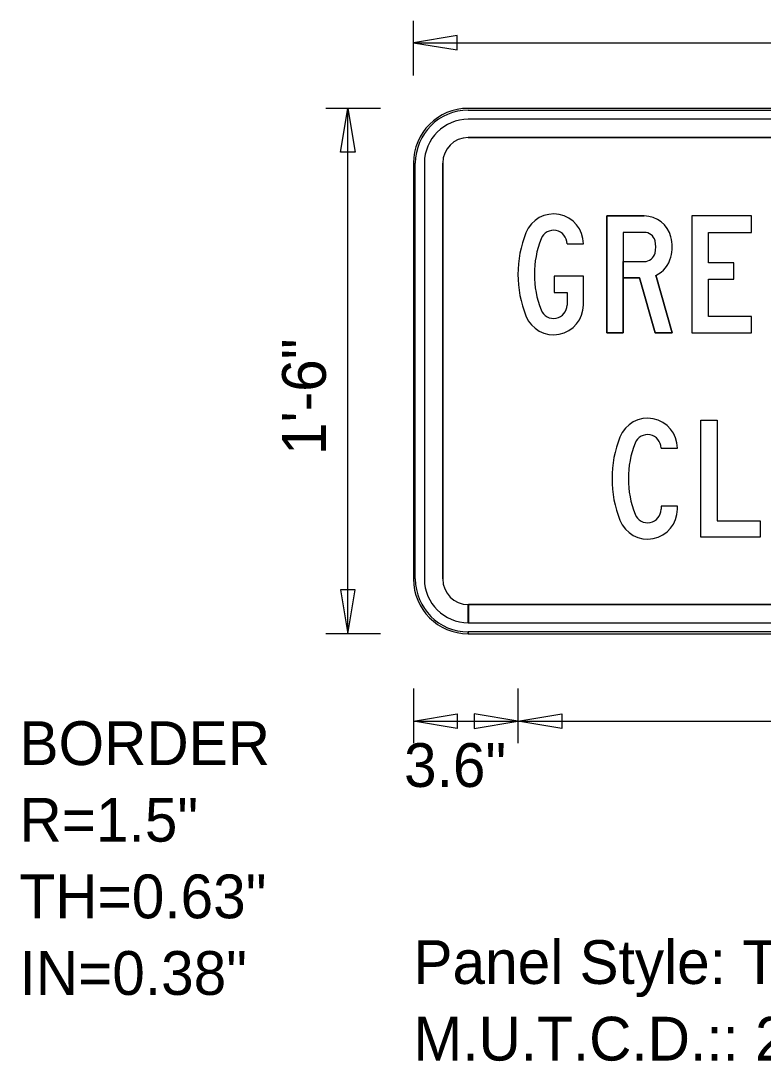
# Model space of a CAD drawing. Extents: x 1788.1 to 1851.2, y 237.2 to 283.4.
# Drawn here: x 1838.393 to 1840.936, y 274.583 to 278.148 of the extents above; entities that cross this region are included whole.
import ezdxf

# ---------------------------------------------------------------- set-up
doc = ezdxf.new("R2010")
doc.units = 0
for name, color, linetype in [('GSBWFILL', 7, 'Continuous'), ('GSCOLORFILL', 7, 'Continuous'), ('GSDIMS', 7, 'Continuous'), ('GSOUTLINE', 7, 'Continuous')]:
    doc.layers.add(name, color=color, linetype=linetype)

msp = doc.modelspace()

# ---------------------------------------------------------------- linework, layer by layer
at = {"layer": 'GSBWFILL'}
for p, q in [((1842.5504, 277.848), (1839.9254, 277.848)), ((1842.5504, 277.8105), (1839.9254, 277.8105)), ((1839.9254, 277.748), (1842.5504, 277.748)), ((1839.7379, 277.6605), (1839.7379, 276.2355)), ((1839.7754, 277.6605), (1839.7754, 276.2355)), ((1839.8379, 276.2355), (1839.8379, 277.6605)), ((1840.2639, 277.3842), (1840.3199, 277.3842)), ((1840.5284, 277.3232), (1840.5284, 277.3232)), ((1840.2639, 277.2172), (1840.2639, 277.1742)), ((1840.5859, 276.6842), (1840.6419, 276.6842)), ((1839.9254, 276.0855), (1839.9254, 276.148)), ((1842.5504, 276.148), (1839.926, 276.148)), ((1839.926, 276.148), (1839.926, 276.0855)), ((1839.926, 276.0855), (1842.5504, 276.0855)), ((1839.9254, 276.048), (1842.5504, 276.048))]:
    msp.add_line(p, q, dxfattribs=at)
for points in [[(1840.5284, 277.4232), (1840.4559, 277.4232), (1840.4559, 277.0792), (1840.3999, 277.0792), (1840.3999, 277.4792), (1840.5284, 277.4792)], [(1840.5679, 277.2759), (1840.6239, 277.0792), (1840.5657, 277.0792), (1840.5121, 277.2672), (1840.4559, 277.2672), (1840.4559, 277.3232), (1840.5284, 277.3232)], [(1840.3199, 277.1742), (1840.3199, 277.2732), (1840.2199, 277.2732), (1840.2199, 277.2172), (1840.2639, 277.2172)], [(1840.6419, 276.4742), (1840.6419, 276.4852), (1840.5859, 276.4852), (1840.5859, 276.4742)]]:
    msp.add_lwpolyline(points, dxfattribs=at)
for points in [[(1840.7479, 277.1352), (1840.7479, 277.2632), (1840.8355, 277.2632), (1840.8355, 277.3192), (1840.7479, 277.3192), (1840.7479, 277.4232), (1840.8959, 277.4232), (1840.8959, 277.4792), (1840.6919, 277.4792), (1840.6919, 277.0792), (1840.8959, 277.0792), (1840.8959, 277.1352)], [(1840.7219, 276.7792), (1840.7779, 276.7792), (1840.7779, 276.4352), (1840.9259, 276.4352), (1840.9259, 276.3792), (1840.7219, 276.3792)]]:
    msp.add_lwpolyline(points, close=True, dxfattribs=at)
for centre, radius, start, end in [((1839.9254, 277.6605), 0.1875, 90, 180), ((1839.9254, 277.6605), 0.15, 90, 180), ((1839.9254, 277.6605), 0.0875, 90, 180), ((1840.5284, 277.3852), 0.094, 13.8865, 90), ((1840.5284, 277.3852), 0.038, 13.8865, 90), ((1840.4799, 277.3732), 0.144, 346.1135, 13.8865), ((1840.4799, 277.3732), 0.088, 346.1135, 13.8865), ((1840.5284, 277.3612), 0.038, 270, 346.1135), ((1840.5284, 277.3612), 0.094, 294.8221, 346.1135), ((1840.5399, 276.6842), 0.102, 0, 158.4314), ((1840.5399, 276.6842), 0.046, 0, 158.4314), ((1840.8055, 276.5792), 0.3876, 158.4314, 201.5686), ((1840.8055, 276.5792), 0.3316, 158.4314, 201.5686), ((1840.5399, 276.4742), 0.102, 201.5686, 0), ((1840.5399, 276.4742), 0.046, 201.5686, 0), ((1839.9254, 276.2355), 0.1875, 180, 270), ((1839.9254, 276.2355), 0.15, 180, 270), ((1839.9254, 276.2355), 0.0875, 180, 270)]:
    msp.add_arc(centre, radius, start, end, dxfattribs=at)
for centre, major_axis, start_param, end_param in [((1840.2179, 277.3842), (0, 0.102), 4.712389, 7.477539), ((1840.4835, 277.2792), (0, 0.3876), 1.194353, 1.947239), ((1840.4835, 277.2792), (0, 0.3316), 1.194353, 1.947239), ((1840.2179, 277.3842), (0, 0.046), 4.712389, 7.477539), ((1840.2179, 277.1742), (0, 0.102), 1.947239, 4.712389), ((1840.2179, 277.1742), (0, 0.046), 1.947239, 4.712389)]:
    msp.add_ellipse(centre, major_axis=major_axis, ratio=0.999991, start_param=start_param, end_param=end_param, dxfattribs=at)
at = {"layer": 'GSCOLORFILL'}
for p, q in [((1842.5504, 277.848), (1839.9254, 277.848)), ((1842.5504, 277.848), (1839.9254, 277.848)), ((1839.9254, 277.8417), (1842.5504, 277.8417)), ((1842.5504, 277.8105), (1839.9254, 277.8105)), ((1839.9254, 277.748), (1842.5504, 277.748)), ((1839.7379, 277.6605), (1839.7379, 276.2355)), ((1839.7379, 277.6605), (1839.7379, 276.2355)), ((1839.7441, 276.2355), (1839.7441, 277.6605)), ((1839.7754, 277.6605), (1839.7754, 276.2355)), ((1839.8379, 276.2355), (1839.8379, 277.6605)), ((1840.2639, 277.3842), (1840.3199, 277.3842)), ((1840.5284, 277.3232), (1840.5284, 277.3232)), ((1840.2639, 277.2172), (1840.2639, 277.1742)), ((1840.5859, 276.6842), (1840.6419, 276.6842)), ((1839.9254, 276.0855), (1839.9254, 276.148)), ((1842.5504, 276.148), (1839.926, 276.148)), ((1839.926, 276.148), (1839.926, 276.0855)), ((1839.926, 276.0855), (1842.5504, 276.0855)), ((1839.9254, 276.048), (1839.9254, 276.0542)), ((1839.9254, 276.048), (1842.5504, 276.048)), ((1842.5504, 276.0542), (1839.9255, 276.0542)), ((1839.9255, 276.0542), (1839.9255, 276.048)), ((1839.9255, 276.048), (1842.5504, 276.048))]:
    msp.add_line(p, q, dxfattribs=at)
for points in [[(1840.5284, 277.4232), (1840.4559, 277.4232), (1840.4559, 277.0792), (1840.3999, 277.0792), (1840.3999, 277.4792), (1840.5284, 277.4792)], [(1840.5679, 277.2759), (1840.6239, 277.0792), (1840.5657, 277.0792), (1840.5121, 277.2672), (1840.4559, 277.2672), (1840.4559, 277.3232), (1840.5284, 277.3232)], [(1840.3199, 277.1742), (1840.3199, 277.2732), (1840.2199, 277.2732), (1840.2199, 277.2172), (1840.2639, 277.2172)], [(1840.6419, 276.4742), (1840.6419, 276.4852), (1840.5859, 276.4852), (1840.5859, 276.4742)]]:
    msp.add_lwpolyline(points, dxfattribs=at)
for points in [[(1840.7479, 277.1352), (1840.7479, 277.2632), (1840.8355, 277.2632), (1840.8355, 277.3192), (1840.7479, 277.3192), (1840.7479, 277.4232), (1840.8959, 277.4232), (1840.8959, 277.4792), (1840.6919, 277.4792), (1840.6919, 277.0792), (1840.8959, 277.0792), (1840.8959, 277.1352)], [(1840.7219, 276.7792), (1840.7779, 276.7792), (1840.7779, 276.4352), (1840.9259, 276.4352), (1840.9259, 276.3792), (1840.7219, 276.3792)]]:
    msp.add_lwpolyline(points, close=True, dxfattribs=at)
for centre, radius, start, end in [((1839.9254, 277.6605), 0.1875, 90, 180), ((1839.9254, 277.6605), 0.1875, 90, 180), ((1839.9254, 277.6605), 0.1812, 90, 180), ((1839.9254, 277.6605), 0.15, 90, 180), ((1839.9254, 277.6605), 0.0875, 90, 180), ((1840.5284, 277.3852), 0.094, 13.8865, 90), ((1840.5284, 277.3852), 0.038, 13.8865, 90), ((1840.4799, 277.3732), 0.144, 346.1135, 13.8865), ((1840.4799, 277.3732), 0.088, 346.1135, 13.8865), ((1840.5284, 277.3612), 0.038, 270, 346.1135), ((1840.5284, 277.3612), 0.094, 294.8221, 346.1135), ((1840.5399, 276.6842), 0.102, 0, 158.4314), ((1840.5399, 276.6842), 0.046, 0, 158.4314), ((1840.8055, 276.5792), 0.3876, 158.4314, 201.5686), ((1840.8055, 276.5792), 0.3316, 158.4314, 201.5686), ((1840.5399, 276.4742), 0.102, 201.5686, 0), ((1840.5399, 276.4742), 0.046, 201.5686, 0), ((1839.9254, 276.2355), 0.1875, 180, 270), ((1839.9254, 276.2355), 0.1875, 180, 270), ((1839.9254, 276.2355), 0.1812, 180, 270), ((1839.9254, 276.2355), 0.15, 180, 270), ((1839.9254, 276.2355), 0.0875, 180, 270)]:
    msp.add_arc(centre, radius, start, end, dxfattribs=at)
for centre, major_axis, start_param, end_param in [((1840.2179, 277.3842), (0, 0.102), 4.712389, 7.477539), ((1840.4835, 277.2792), (0, 0.3876), 1.194353, 1.947239), ((1840.4835, 277.2792), (0, 0.3316), 1.194353, 1.947239), ((1840.2179, 277.3842), (0, 0.046), 4.712389, 7.477539), ((1840.2179, 277.1742), (0, 0.102), 1.947239, 4.712389), ((1840.2179, 277.1742), (0, 0.046), 1.947239, 4.712389)]:
    msp.add_ellipse(centre, major_axis=major_axis, ratio=0.999991, start_param=start_param, end_param=end_param, dxfattribs=at)
at = {"layer": 'GSDIMS'}
for p, q in [((1839.7379, 277.9605), (1839.7379, 278.148)), ((1839.7379, 278.073), (1842.7379, 278.073)), ((1839.7379, 277.9605), (1839.7379, 277.9605)), ((1839.6254, 277.848), (1839.4379, 277.848)), ((1839.5129, 276.048), (1839.5129, 277.848)), ((1839.6254, 277.848), (1839.6254, 277.848)), ((1839.6254, 276.048), (1839.4379, 276.048)), ((1839.6254, 276.048), (1839.6254, 276.048)), ((1839.7379, 275.8605), (1839.7379, 275.673)), ((1839.7379, 275.8605), (1839.7379, 275.673)), ((1840.0959, 275.8605), (1840.0959, 275.673)), ((1840.0959, 275.8605), (1840.0959, 275.673)), ((1839.7379, 275.748), (1840.0959, 275.748)), ((1840.0959, 275.748), (1842.3799, 275.748))]:
    msp.add_line(p, q, dxfattribs=at)
for points in [[(1839.7379, 278.073), (1839.8879, 278.048), (1839.8879, 278.098)], [(1839.5129, 277.848), (1839.5379, 277.698), (1839.4879, 277.698)], [(1839.5129, 276.048), (1839.5379, 276.198), (1839.4879, 276.198)], [(1839.7379, 275.748), (1839.8879, 275.773), (1839.8879, 275.723)], [(1840.0959, 275.748), (1839.9459, 275.773), (1839.9459, 275.723)], [(1840.0959, 275.748), (1840.2459, 275.773), (1840.2459, 275.723)]]:
    msp.add_lwpolyline(points, close=True, dxfattribs=at)
at = {"layer": 'GSOUTLINE'}
for p, q in [((1842.5504, 277.848), (1839.9254, 277.848)), ((1842.5504, 277.8105), (1839.9254, 277.8105)), ((1842.5504, 277.748), (1839.9254, 277.748)), ((1839.7379, 277.6605), (1839.7379, 276.2355)), ((1839.7754, 277.6605), (1839.7754, 276.2355)), ((1839.8379, 277.6605), (1839.8379, 276.2355)), ((1840.5284, 277.4792), (1840.3999, 277.4792)), ((1840.5284, 277.4232), (1840.5284, 277.4232)), ((1840.2639, 277.3842), (1840.3199, 277.3842)), ((1840.2639, 277.2172), (1840.2639, 277.1742)), ((1840.5859, 276.6842), (1840.6419, 276.6842)), ((1839.9254, 276.148), (1842.5504, 276.148)), ((1839.9254, 276.0855), (1842.5504, 276.0855)), ((1839.9254, 276.048), (1842.5504, 276.048))]:
    msp.add_line(p, q, dxfattribs=at)
for points in [[(1840.3999, 277.4792), (1840.3999, 277.0792), (1840.4559, 277.0792), (1840.4559, 277.2672), (1840.5121, 277.2672), (1840.5657, 277.0792), (1840.6239, 277.0792), (1840.5679, 277.2759)], [(1840.5284, 277.4232), (1840.4559, 277.4232), (1840.4559, 277.3232), (1840.5284, 277.3232)], [(1840.3199, 277.1742), (1840.3199, 277.2732), (1840.2199, 277.2732), (1840.2199, 277.2172), (1840.2639, 277.2172)], [(1840.6419, 276.4742), (1840.6419, 276.4852), (1840.5859, 276.4852), (1840.5859, 276.4742)]]:
    msp.add_lwpolyline(points, dxfattribs=at)
for points in [[(1840.7479, 277.1352), (1840.7479, 277.2632), (1840.8355, 277.2632), (1840.8355, 277.3192), (1840.7479, 277.3192), (1840.7479, 277.4232), (1840.8959, 277.4232), (1840.8959, 277.4792), (1840.6919, 277.4792), (1840.6919, 277.0792), (1840.8959, 277.0792), (1840.8959, 277.1352)], [(1840.7219, 276.7792), (1840.7779, 276.7792), (1840.7779, 276.4352), (1840.9259, 276.4352), (1840.9259, 276.3792), (1840.7219, 276.3792)]]:
    msp.add_lwpolyline(points, close=True, dxfattribs=at)
for centre, radius, start, end in [((1839.9254, 277.6605), 0.1875, 90, 180), ((1839.9254, 277.6605), 0.15, 90, 180), ((1839.9254, 277.6605), 0.0875, 90, 180), ((1840.5284, 277.3852), 0.094, 13.8865, 90), ((1840.5284, 277.3852), 0.038, 13.8865, 90), ((1840.4799, 277.3732), 0.144, 346.1135, 13.8865), ((1840.4799, 277.3732), 0.088, 346.1135, 13.8865), ((1840.5284, 277.3612), 0.038, 270, 346.1135), ((1840.5284, 277.3612), 0.094, 294.8221, 346.1135), ((1840.5399, 276.6842), 0.102, 0, 158.4314), ((1840.5399, 276.6842), 0.046, 0, 158.4314), ((1840.8055, 276.5792), 0.3876, 158.4314, 201.5686), ((1840.8055, 276.5792), 0.3316, 158.4314, 201.5686), ((1840.5399, 276.4742), 0.102, 201.5686, 0), ((1840.5399, 276.4742), 0.046, 201.5686, 0), ((1839.9254, 276.2355), 0.1875, 180, 270), ((1839.9254, 276.2355), 0.15, 180, 270), ((1839.9254, 276.2355), 0.0875, 180, 270)]:
    msp.add_arc(centre, radius, start, end, dxfattribs=at)
for centre, major_axis, start_param, end_param in [((1840.2179, 277.3842), (0, 0.102), 4.712389, 7.477539), ((1840.4835, 277.2792), (0, 0.3876), 1.194353, 1.947239), ((1840.4835, 277.2792), (0, 0.3316), 1.194353, 1.947239), ((1840.2179, 277.3842), (0, 0.046), 4.712389, 7.477539), ((1840.2179, 277.1742), (0, 0.102), 1.947239, 4.712389), ((1840.2179, 277.1742), (0, 0.046), 1.947239, 4.712389)]:
    msp.add_ellipse(centre, major_axis=major_axis, ratio=0.999991, start_param=start_param, end_param=end_param, dxfattribs=at)

# ---------------------------------------------------------------- texts
at = {"layer": 'GSDIMS'}
msp.add_text('1\'-6"', height=0.15, rotation=90, dxfattribs=at).set_placement((1839.4379, 276.6601))
for s, p in [('BORDER', (1838.3884, 275.598)), ('3.6"', (1839.7055, 275.523)), ('R=1.5"', (1838.3884, 275.3355)), ('TH=0.63"', (1838.3884, 275.073)), ('Panel Style: Traffic Control.ssi', (1839.7379, 274.848)), ('IN=0.38"', (1838.3884, 274.8105)), ('M.U.T.C.D.:: 2009 Edition', (1839.7379, 274.5855))]:
    msp.add_text(s, height=0.15, dxfattribs=at).set_placement(p)

doc.saveas('drawing.dxf')
